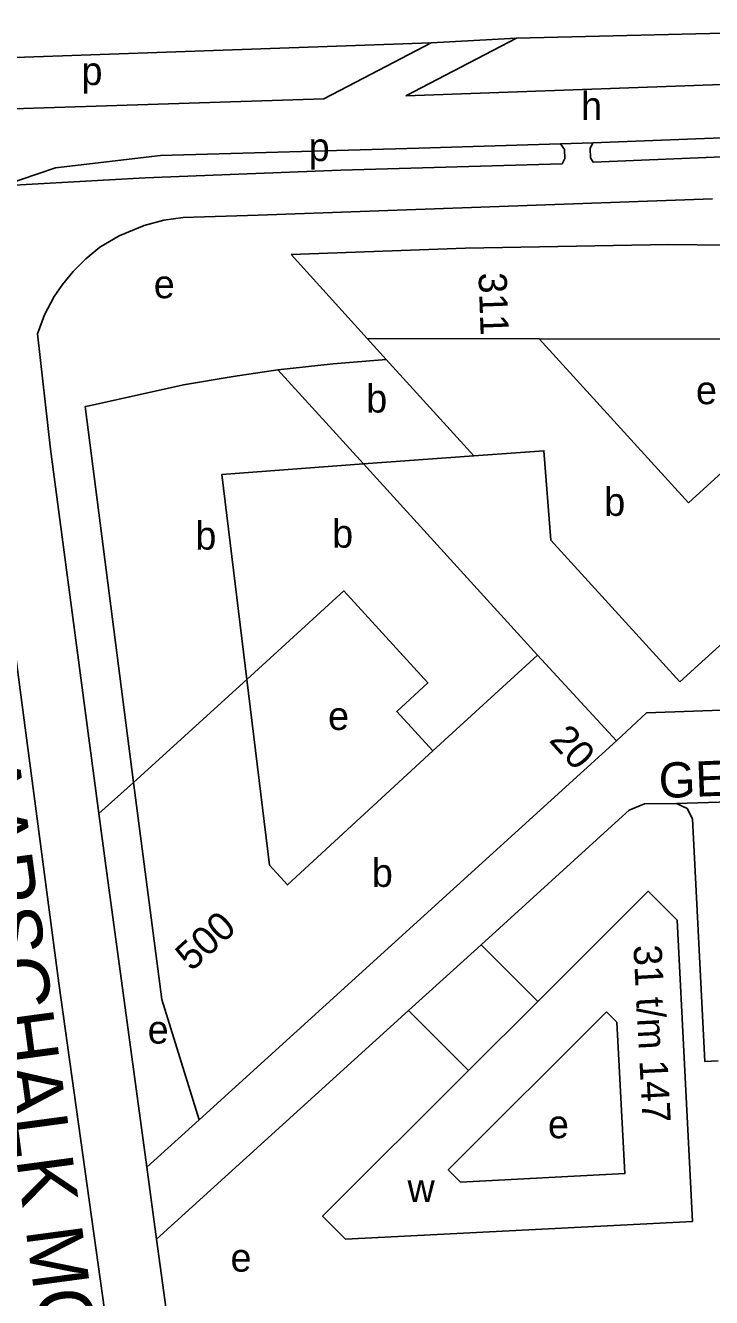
# Model space of a CAD drawing. Extents: x 159294 to 161936, y 384538 to 386517.
# Drawn here: x 161120.1 to 161217.5, y 386304 to 386484.5 of the extents above; entities that cross this region are included whole.
import ezdxf

# ---------------------------------------------------------------- set-up
doc = ezdxf.new("R2010")
doc.units = 0
for name, color, linetype in [('BLT_Basislijn', 7, 'Continuous'), ('BLT_Bebouwing', 7, 'Continuous'), ('BLT_Centroide', 7, 'Continuous'), ('BLT_Huisnummer_reeks', 7, 'Continuous'), ('BLT_Huisnummer_zonder_bebouwing', 7, 'Continuous'), ('BLT_Onderdoorgang_en_onderverdeling', 7, 'Continuous'), ('BLT_Onderverdeling_panden', 7, 'Continuous'), ('BLT_Straatnaam', 7, 'Continuous'), ('BLT_Straatnaam_hoofdweg', 7, 'Continuous'), ('BLT_Vlakafsluiter', 7, 'Continuous')]:
    doc.layers.add(name, color=color, linetype=linetype)

msp = doc.modelspace()

# ---------------------------------------------------------------- linework, layer by layer
at = {"layer": 'BLT_Basislijn'}
for p, q in [((161324.03, 386479.85), (161174.09, 386474.55)), ((161168.09, 386477.06), (161162.49, 386474.14)), ((161196.62, 386466.95), (161196.65, 386465.65)), ((161200.29, 386465.76), (161200.25, 386467.05)), ((161217.61, 386459.92), (161153.14, 386457.6)), ((161124.87, 386348.64), (161111.25, 386451.79)), ((161130.54, 386372.73), (161123.7, 386424.39)), ((161203.99, 386383.05), (161208.26, 386386.99)), ((161228.06, 386387.74), (161208.26, 386386.99)), ((161212.5, 386374.16), (161222.9, 386374.48)), ((161184.78, 386354.09), (161174.5, 386344.77)), ((161184.78, 386354.09), (161192.83, 386346.05)), ((161133.12, 386289.79), (161124.87, 386348.64)), ((161174.5, 386344.77), (161138.74, 386312.31)), ((161183.01, 386336.26), (161174.5, 386344.77)), ((161137.35, 386322.53), (161138.74, 386312.31)), ((161138.74, 386312.31), (161141.17, 386294.47))]:
    msp.add_line(p, q, dxfattribs=at)
for points in [[(161189.81, 386482.75), (161264.26, 386484.53), (161279.03, 386481.7), (161323.9, 386483.33)], [(161174.09, 386474.55), (161189.81, 386482.75)], [(161094.48, 386479.13), (161177.69, 386482.07)], [(161168.09, 386477.06), (161177.69, 386482.07)], [(161094.83, 386471.96), (161162.49, 386474.14)], [(161196.05, 386467.72), (161175.96, 386467.11)], [(161196.62, 386466.95), (161196.05, 386467.72)], [(161200.25, 386467.05), (161200.63, 386467.87)], [(161200.63, 386467.87), (161222.58, 386468.71)], [(161116.88, 386461.78), (161124.39, 386464.35), (161139.29, 386466.08), (161175.96, 386467.11)], [(161222.43, 386466.04), (161200.71, 386465.12), (161200.29, 386465.76)], [(161196.65, 386465.65), (161196.28, 386464.89), (161164.89, 386463.98)], [(161164.89, 386463.98), (161137.15, 386462.91), (161116.88, 386461.78)], [(161153.14, 386457.6), (161142.52, 386457.29), (161139.78, 386456.9), (161136.97, 386456.16), (161133.42, 386454.67), (161130.7, 386453.08), (161128.71, 386451.43), (161126.92, 386449.62), (161125.39, 386447.77), (161124.22, 386446.07), (161122.85, 386443.48), (161121.84, 386440.77), (161123.7, 386424.39)], [(161130.54, 386372.73), (161135.49, 386377.11)], [(161212.5, 386374.16), (161207.96, 386374.07), (161205.81, 386373.19), (161204.34, 386371.85), (161184.78, 386354.09)], [(161212.5, 386374.16), (161214.02, 386373.43), (161214.79, 386371.98), (161216.55, 386337.51), (161218.42, 386337.62)], [(161131.46, 386365.99), (161130.54, 386372.73)], [(161137.35, 386322.53), (161131.46, 386365.99)], [(161144.78, 386329.24), (161137.35, 386322.53)]]:
    msp.add_lwpolyline(points, dxfattribs=at)
at = {"layer": 'BLT_Bebouwing'}
for p, q in [((161168.1, 386422.31), (161183.77, 386423.49)), ((161192.77, 386395.19), (161168.1, 386422.31)), ((161183.01, 386336.26), (161192.83, 386346.05))]:
    msp.add_line(p, q, dxfattribs=at)
for points in [[(161279.29, 386451.71), (161258.78, 386452.64), (161258.75, 386451.8), (161251.45, 386451.61), (161251.48, 386452.98), (161211.44, 386453.43), (161182.58, 386452.91), (161157.83, 386452.02)], [(161157.83, 386452.02), (161168.64, 386440.12)], [(161212.99, 386391.38), (161229.92, 386406.79), (161236.69, 386412.95), (161279.29, 386451.71)], [(161168.64, 386440.12), (161171.34, 386437.15)], [(161171.34, 386437.15), (161163.79, 386436.54), (161155.95, 386435.68)], [(161155.95, 386435.68), (161149.62, 386434.74), (161142.56, 386433.52), (161129.18, 386430.58), (161128.63, 386430.45), (161135.49, 386377.11)], [(161183.77, 386423.49), (161193.7, 386424.19), (161194.66, 386411.52), (161212.99, 386391.38)], [(161151.55, 386391.73), (161165.32, 386404.3), (161177.25, 386391.24), (161172.82, 386387.2), (161177.92, 386381.62)], [(161192.77, 386395.19), (161203.99, 386383.05)], [(161151.55, 386391.73), (161154.77, 386365.39)], [(161203.99, 386383.05), (161144.78, 386329.24)], [(161154.77, 386365.39), (161157.34, 386362.58), (161177.92, 386381.62)], [(161144.78, 386329.24), (161139.48, 386346.35), (161135.49, 386377.11)], [(161192.83, 386346.05), (161208.49, 386361.69), (161212.59, 386357.58), (161214.79, 386314.83), (161165.56, 386312.3), (161162.29, 386315.57), (161183.01, 386336.26)]]:
    msp.add_lwpolyline(points, dxfattribs=at)
msp.add_lwpolyline([(161202.59, 386344.57), (161204.06, 386343.09), (161205.17, 386321.63), (161181.86, 386320.43), (161180.13, 386322.16)], close=True, dxfattribs=at)
at = {"layer": 'BLT_Onderdoorgang_en_onderverdeling'}
for p, q in [((161183.77, 386423.49), (161171.34, 386437.15)), ((161155.95, 386435.68), (161168.1, 386422.31))]:
    msp.add_line(p, q, dxfattribs=at)
at = {"layer": 'BLT_Onderverdeling_panden'}
for p, q in [((161193.03, 386440.07), (161168.64, 386440.12)), ((161239.65, 386439.98), (161193.03, 386440.07)), ((161168.1, 386422.31), (161148, 386420.81)), ((161151.55, 386391.73), (161148, 386420.81)), ((161177.92, 386381.62), (161192.77, 386395.19))]:
    msp.add_line(p, q, dxfattribs=at)
for points in [[(161193.03, 386440.07), (161214.19, 386416.81)], [(161214.19, 386416.81), (161239.65, 386439.98)], [(161135.49, 386377.11), (161151.55, 386391.73)]]:
    msp.add_lwpolyline(points, dxfattribs=at)
at = {"layer": 'BLT_Vlakafsluiter'}
for p, q in [((161177.69, 386482.07), (161189.81, 386482.75)), ((161196.05, 386467.72), (161200.63, 386467.87))]:
    msp.add_line(p, q, dxfattribs=at)

# ---------------------------------------------------------------- texts
at = {"layer": 'BLT_Centroide'}
for s, p in [('p', (161128.1, 386476.07)), ('h', (161198.97, 386471.12)), ('p', (161160.33, 386465.29)), ('e', (161138.35, 386445.83)), ('b', (161168.49, 386429.61)), ('e', (161215.27, 386430.79)), ('b', (161202.26, 386414.95)), ('b', (161144.25, 386410.17)), ('b', (161163.66, 386410.44)), ('e', (161163.08, 386384.57)), ('b', (161169.29, 386362.31)), ('e', (161137.49, 386340.07)), ('e', (161194.27, 386326.64)), ('w', (161174.35, 386317.59)), ('e', (161149.24, 386307.71))]:
    msp.add_text(s, height=4, dxfattribs=at).set_placement(p)
at = {"layer": 'BLT_Huisnummer_reeks'}
for s, rotation, p in [('311', 272.064, (161184.41, 386449.42)), ('20', 312.2907, (161194.3, 386383.03)), ('500', 42.2896, (161143.69, 386350.21))]:
    msp.add_text(s, height=4, rotation=rotation, dxfattribs=at).set_placement(p)
at = {"layer": 'BLT_Huisnummer_zonder_bebouwing'}
msp.add_text('31 t/m 147', height=4, rotation=273.0017, dxfattribs=at).set_placement((161206.39, 386354))
at = {"layer": 'BLT_Straatnaam'}
msp.add_text('GENERAAL TAYLORPAD', height=5, rotation=2.2363, dxfattribs=at).set_placement((161210.08, 386374.89))
at = {"layer": 'BLT_Straatnaam_hoofdweg'}
msp.add_text('VELDMAARSCHALK MONTGOMERYLAAN', height=7.9999, rotation=277.6475, dxfattribs=at).set_placement((161106.24, 386417.38))

doc.saveas('drawing.dxf')
